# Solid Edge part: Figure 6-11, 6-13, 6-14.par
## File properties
Author: TIET
Template: Iso Metric Part.par
Last saved by: CADCIM
Revision: 3
Application: Solid Edge
Accuracy: 0.990
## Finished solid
Body 1: solid body, 10 faces, 20 edges, 12 vertices.
  Faces by surface: plane 6, cylinder 4
  Edges by curve: line 16, ellipse 4
Bounding box of the edges (mm): 67.490 x 44.466 x 30.000, from (0, 0, 0) to (67.4897, 44.4656, 30).
Cylindrical faces by radius (mm): R5 x4
Planar faces by outward normal: +x 1, +y 1, +z 1, -x 1, -y 1, -z 1
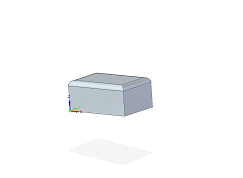
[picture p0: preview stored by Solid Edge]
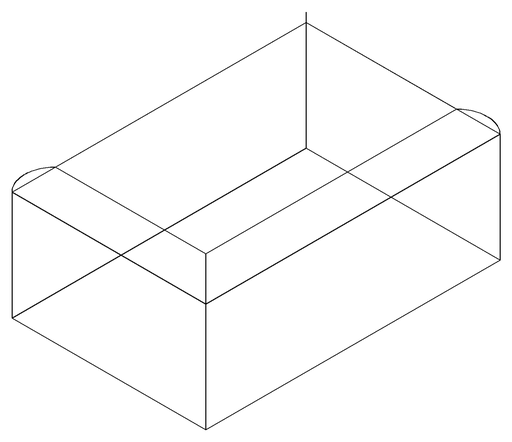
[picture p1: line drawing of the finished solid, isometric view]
